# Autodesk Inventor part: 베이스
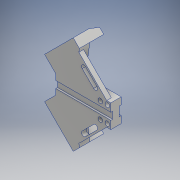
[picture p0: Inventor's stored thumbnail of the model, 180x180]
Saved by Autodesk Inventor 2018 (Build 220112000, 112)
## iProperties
Created: 2020-05
Part Number: 베이스
Material: 알루미늄 6061
Document SubType Name: Modeling
Designer: 1class 18
Density: 2.7 g/cm^3
Appearance: 알루미늄 - 평지
Mass: 571.622 g
Surface Area: 407.173 cm^2
Volume: 211.712 cm^3
Author: 1class 18
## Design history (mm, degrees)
sketch "스케치2"
  geometry: L1 (0, 84.853)-(-64.853, 20); L2 (-64.853, -20)-(0, -84.853); L3 (0, -84.853)-(49.497, -35.355); L4 (49.497, 35.355)-(0, 84.853); L5 (0, 84.853)-(0, -84.853); L6 (-84.853, 0)-(84.853, 0); L7 (-64.853, 20)-(-64.853, -20); L8 (49.497, -35.355)-(30.147, -16.005); L9 (49.497, 35.355)-(30.147, 16.005); L10 (30.147, 16.005)-(30.147, -16.005); 1 further point
  constraints: 20 end point, 4 parallel, 2 midpoint, 2 perpendicular, 2 vertical, 1 horizontal
  dimensions: "d2" = 120 distance of L6.end L1.start; "d3" = 120 distance of L1.start L6.start; "d7" = 20 distance from line of L7 L6.start; "d9" = 135 deg angle of L10 L3; "d10" = 50 distance between parallel lines of L9 L3; "d11" = 120 distance between parallel lines of L3 L1; "d12" = 50 distance between parallel lines of L4 L8; "d13" = 30.14719 distance between parallel lines of L10 L5; "d14" = 95 distance between parallel lines of L10 L7
extrude "돌출1" new body sketch "스케치2" distance "d15" = 18; taper "d16" = 0 deg
sketch "스케치3"
  geometry: L1 (-49.497, -35.355)-(0, -84.853) reference; L2 (0, 84.853)-(-49.497, 35.355) reference; L3 (0, -84.853)-(64.853, -20) reference; L4 (10.607, -74.246)-(0, -84.853); L5 (0, -84.853)-(-49.497, -35.355); L6 (-49.497, -35.355)-(-38.891, -24.749); L7 (-30.147, -16.005)-(-49.497, -35.355) reference; L8 (-38.891, -24.749)-(10.607, -74.246); L9 (-49.497, 35.355)-(-30.147, 16.005) reference; L10 (-38.891, 24.749)-(-49.497, 35.355); L11 (-49.497, 35.355)-(0, 84.853); L12 (64.853, 20)-(0, 84.853) reference; L13 (10.607, 74.246)-(0, 84.853); L14 (10.607, 74.246)-(-38.891, 24.749); 1 further point
  constraints: 16 end point, 4 collinear, 4 point on line, 2 parallel, 1 perpendicular
  dimensions: "d19" = 15 distance between parallel lines of L1 L8; "d20" = 15 distance between parallel lines of L2 L14
extrude "돌출2" join sketch "스케치3" distance "d21" = 24; taper "d22" = 0 deg
sketch "스케치4"
  geometry: L1 (-30.147, -8)-(64.853, -8); L2 (-30.147, 8)-(64.853, 8); L3 (-30.147, 16.005)-(-30.147, -16.005) reference; L4 (64.853, -20)-(64.853, 20) reference; L5 (64.853, -8)-(64.853, 8); L6 (-30.147, -8)-(-30.147, 8); 1 further point
  constraints: 8 end point, 4 point on line, 2 horizontal, 1 collinear
  dimensions: "d23" = 16 distance between parallel lines of L2 L1; "d24" = 8 distance from line of L1 point (0, 0)
extrude "돌출3" cut sketch "스케치4" distance "d26" = 3.5; taper "d27" = 0 deg
sketch "스케치5"
  geometry: L1 (-30.147, 6)-(64.853, 6); L2 (-30.147, -6)-(64.853, -6); L3 (-30.147, 8)-(-30.147, 16.005) reference; L4 (-30.147, 6)-(-30.147, -6); L5 (-30.147, -16.005)-(-30.147, 16.005) reference; L6 (64.853, 20)-(64.853, -20) reference; L7 (64.853, 6)-(64.853, -6); 1 further point
  constraints: 8 end point, 5 point on line, 2 horizontal
  dimensions: "d28" = 12 distance between parallel lines of L2 L1; "d29" = 6 distance from line of point (0, 0) L2
extrude "돌출4" cut sketch "스케치5" distance "d30" = 3; taper "d31" = 0 deg
sketch "스케치6"
  geometry: L1 (-49.497, -35.355)-(0, -84.853) reference; L2 (10.607, -74.246)-(64.853, -20) reference; L3 (64.853, -8)-(-30.147, -8) reference; L4 (0, -84.853)-(10.607, -74.246) reference; L5 (10.607, -74.246)-(7.071, -49.497); L6 (7.071, -49.497)-(36.569, -20); L7 (36.569, -20)-(64.853, -20); 1 further point
  constraints: 6 end point, 2 parallel, 1 point on line
  dimensions: "d35" = 20 distance between parallel lines of L2 L6; "d36" = 20 distance from line of point (0, 0) L7; "d38" = 126.87 deg angle of L6 L5
extrude "돌출5" cut sketch "스케치6" distance "d39" = 10; taper "d40" = 0 deg
sketch "스케치7"
  geometry: L1 (9.723, -68.059)-(57.782, -20); L2 (64.853, -20)-(10.607, -74.246) reference; L3 (10.607, -74.246)-(7.071, -49.497) reference; L4 (10.607, -74.246)-(9.723, -68.059); L5 (36.569, -20)-(64.853, -20) reference; L6 (64.853, -20)-(57.782, -20); 1 further point
  constraints: 6 end point, 2 point on line, 1 parallel
  dimensions: "d41" = 5 distance between parallel lines of L1 L2
extrude "돌출6" cut sketch "스케치7" distance "d42" = 347.25; taper "d43" = 0 deg
sketch "스케치8"
  geometry: L1 (18.385, -49.497)-(38.184, -29.698); L2 (15.556, -46.669)-(35.355, -26.87); L3 (41.012, -32.527)-(21.213, -52.326); L4 (9.723, -68.059)-(57.782, -20) reference; L5 (0, -84.853)-(10.607, -74.246) reference; L6 (-49.497, -35.355)-(0, -84.853) reference; A1 r 4 centre (18.385, -49.497) between (15.556, -46.669) and (21.213, -52.326); A2 r 4 centre (38.184, -29.698) between (41.012, -32.527) and (35.355, -26.87); 2 further points
  constraints: 8 end point, 4 point on circle, 4 tangent, 2 centre point, 2 parallel, 1 midpoint
  dimensions: "d44" = 12 distance from line of L5 point (28.284, -39.598); "d45" = 38 distance from line of L1.start L6; "d46" = 8 distance between parallel lines of L2 L3; "d48" = 66 distance from line of L1.end L6
extrude "돌출7" cut sketch "스케치8" distance "d49" = 50; taper "d50" = 0 deg
sketch "스케치9"
  geometry: L1 (0, 0)-(0, 42) reference; L2 (0, 42)-(15, 42) reference; L3 (0, 0)-(0, 42) reference; L4 (0, 27)-(5, 42); L5 (0, 27)-(0, 42); L6 (5, 42)-(0, 42); 1 further point
  constraints: 6 end point, 2 point on line, 1 collinear, 1 perpendicular
  dimensions: "d53" = 5 distance of L1.end L4.end; "d54" = 15 distance from line of L4.start L2
extrude "돌출8" cut sketch "스케치9" distance "d55" = 91.25; taper "d56" = 0 deg
sketch "스케치11"
  geometry: L1 (64.853, -6)-(64.853, -20) reference; L2 (64.853, 20)-(64.853, 6) reference; 5 further points
  dimensions: "d66" = 28 distance of point (58.853, 14) point (58.853, -14); "d67" = 14 vertical distance of point (0, 0) point (58.853, -14); "d68" = 28 distance of point (46.853, 14) point (46.853, -14); "d69" = 14 vertical distance of point (0, 0) point (46.853, -14); "d70" = 6 distance from line of L1 point (58.853, -14); "d71" = 6 distance from line of L2 point (58.853, 14); "d72" = 12 distance of point (46.853, -14) point (58.853, -14); "d73" = 12 distance of point (46.853, 14) point (58.853, 14)
hole "구멍1" sketch "스케치11" at (58.853, -14), (58.853, 14), (46.853, 14), (46.853, -14) diameter "d74" = 4.5; stored, may be unused: countersink angle "d78" = 90 deg, drill point angle "d80" = 0 deg; dims "d75" = 6, "d76" = 8, "d77" = 10, "d79" = 18
sketch "스케치12"
  geometry: L1 (10.607, -74.246)-(-38.891, -24.749) reference; L2 (-49.497, -35.355)-(-45.962, -31.82) reference; 2 further points
  constraints: 1 other
  dimensions: "d81" = 5 distance from line of L1 point (-17.678, -53.033); "d82" = 35 distance from line of point (-17.678, -53.033) L2
feature "엠보싱1" sketch "스케치12" dims "d2" = 120, "d83" = 0.5, "d84" = 0
fillet "모깎기1" dims "d85" = 5
fillet "모깎기2" dims "d86" = 5
node "솔리드1"
mirror "미러1"
mirror "미러2"
other parameters: "d8" = 95, "d17" = 15, "d18" = 15
